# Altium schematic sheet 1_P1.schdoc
size 441 x 327 mm; Symbol: Drawing-Symbol_A4; Device: Drawing-Symbol_A4; @Project Name: LC86G-PA Breakout Board V2; @Page Count: 1; @Update Date: 2025-05-25; @Create Date: 2025-05-26; @Schematic Name: Schematic1_1; @Page No: 1; @Page Name: P1; Company: EasyEDA.com; Version: V1.0; Page Size: A4; @Create Time: 00:19:22; @Update Time: 19:19:22; Width: 1700; Height: 1250; Region Start: 1; X Region Count: 6; Y Region Count: 4; Blade Width: 10; Title Block Position: 3; @Board Name: Board1_1
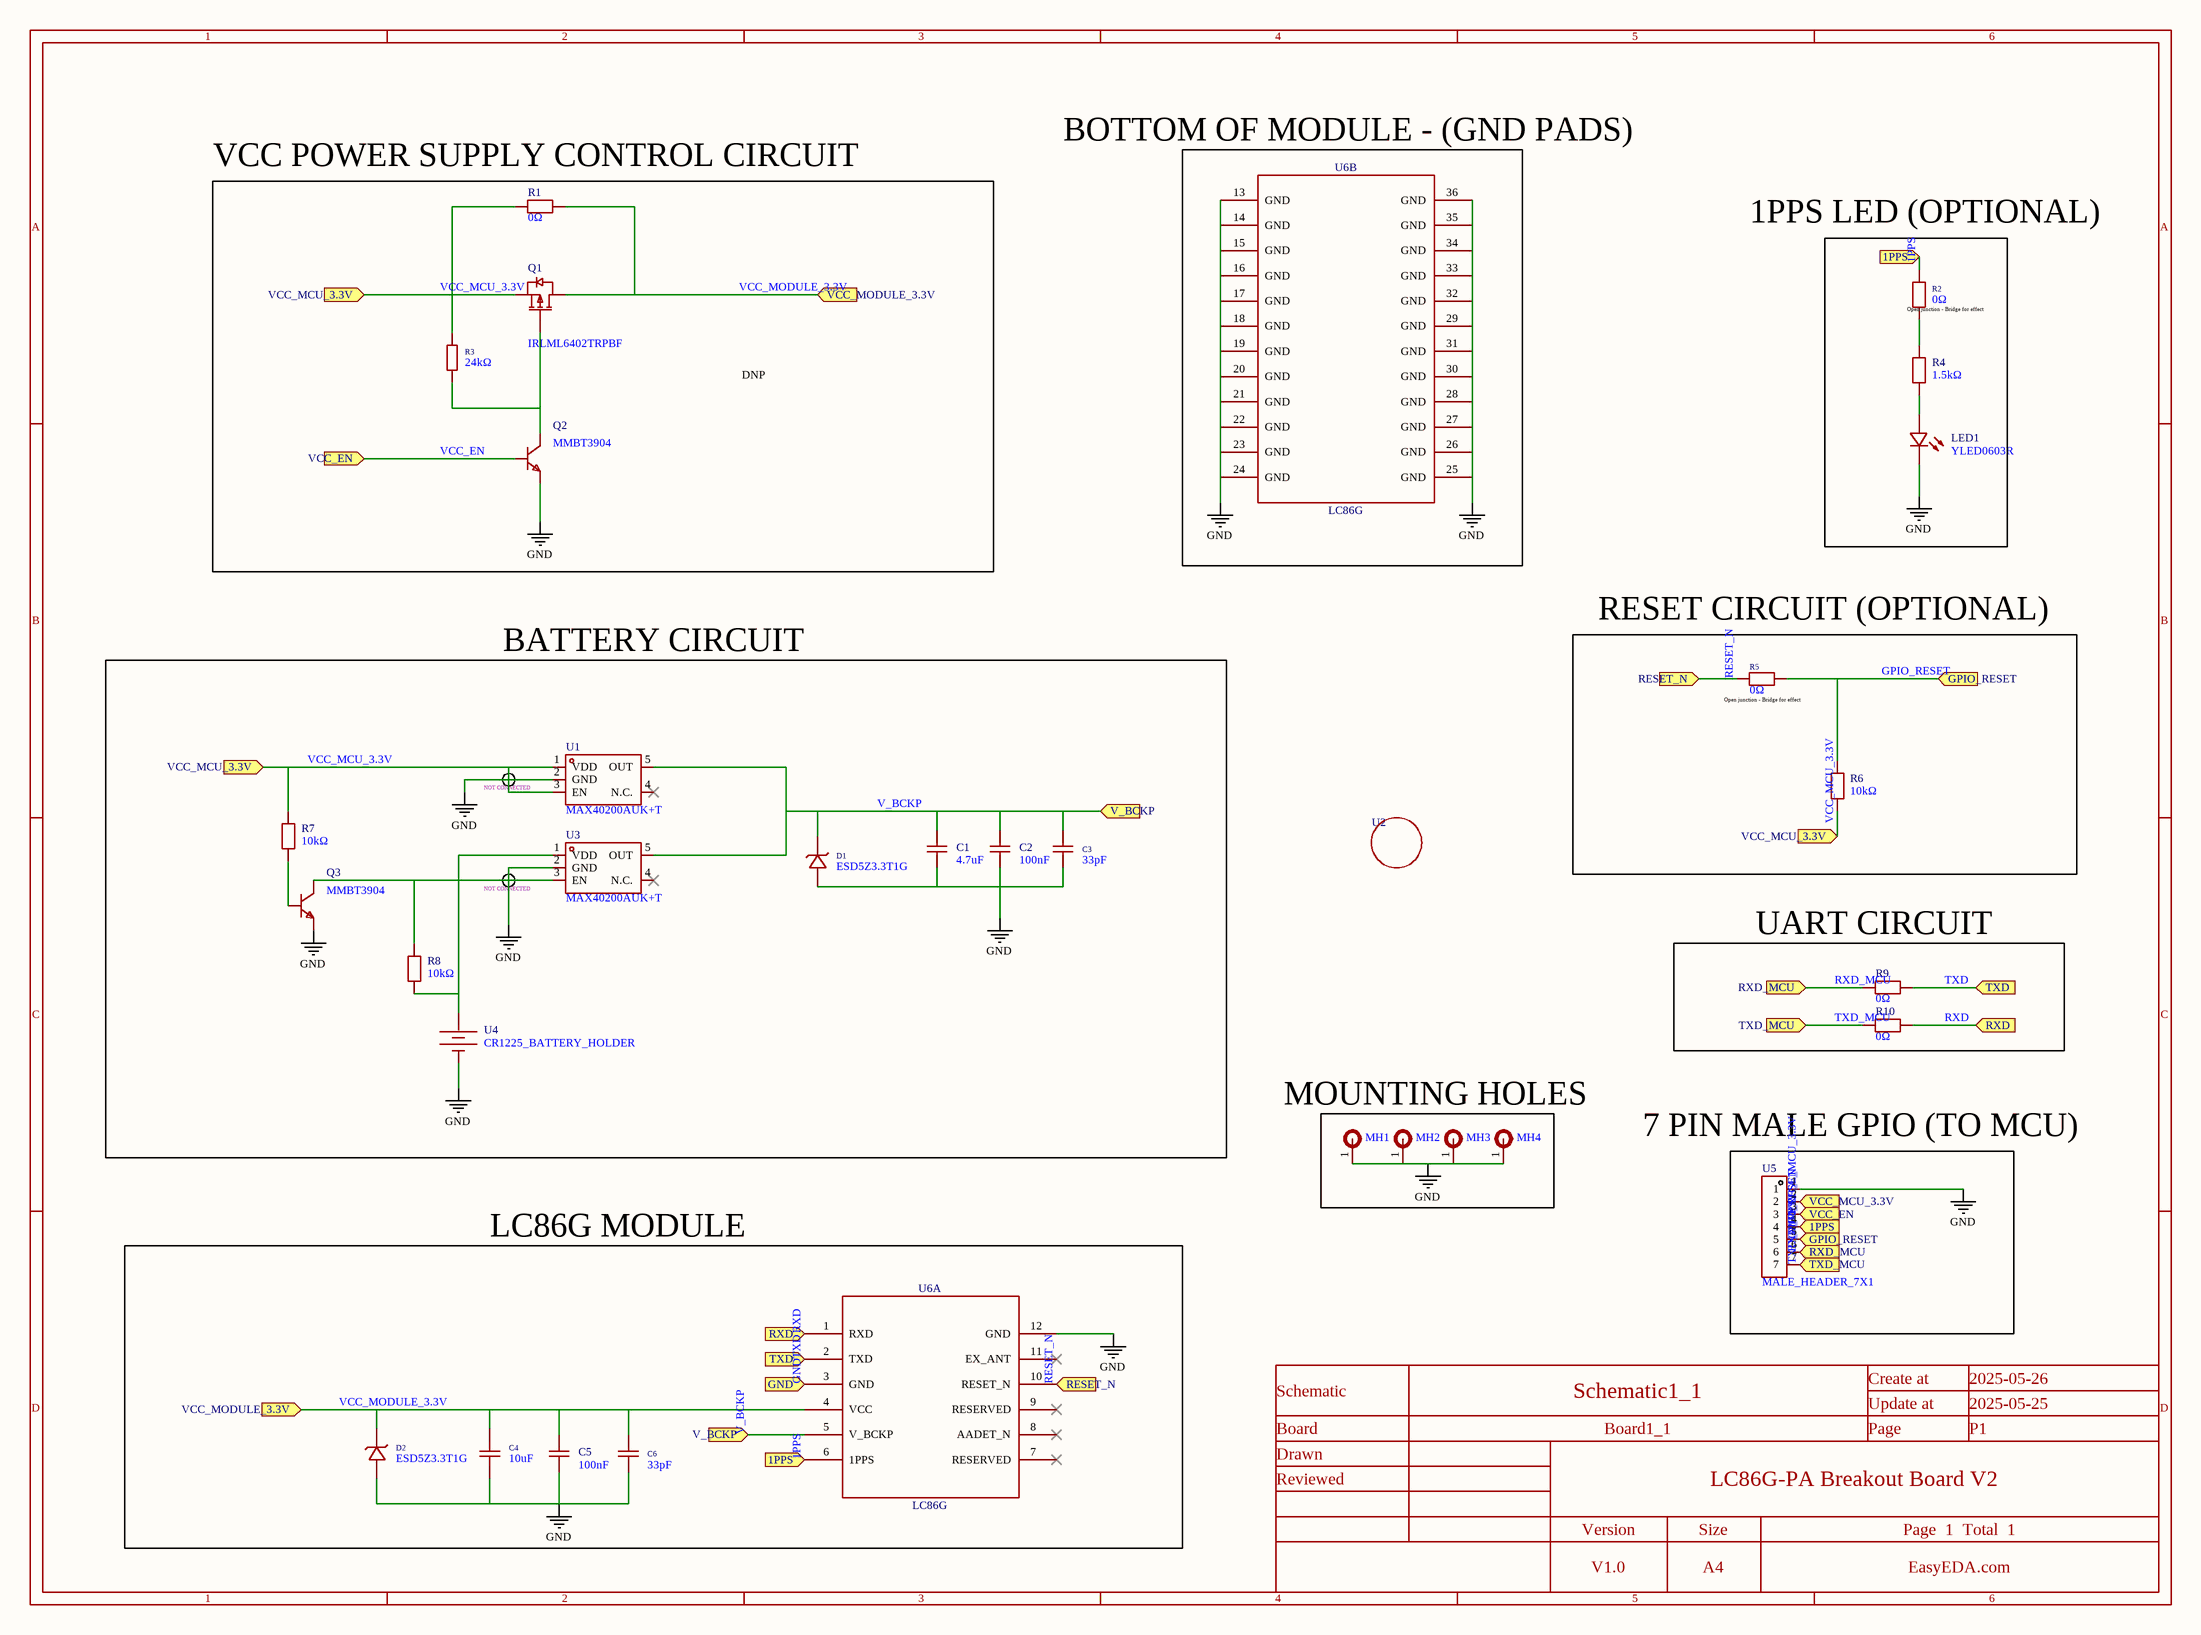
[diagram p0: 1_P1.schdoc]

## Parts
C1  4.7uF  [C0603]
C2  100nF  [C0603]
C3  33pF  [C0603]
C4  10uF  [C0603]
C5  100nF  [C0603]
C6  33pF  [C0603]
D1  ESD5Z3.3T1G  [SOD-523F_L1.2-W0.8-LS1.7-RD]
D2  ESD5Z3.3T1G  [SOD-523F_L1.2-W0.8-LS1.7-RD]
LED1  YLED0603R  [LED0603-FD]
MH1  (no value)  [MH_7.5x2.7MM]
MH2  (no value)  [MH_7.5x2.7MM]
MH3  (no value)  [MH_7.5x2.7MM]
MH4  (no value)  [MH_7.5x2.7MM]
Q1  IRLML6402TRPBF  [SOT-23-3_L2.9-W1.6-P1.90-LS2.8-BR]
Q2  MMBT3904  [SOT-23-3_L2.9-W1.4-P1.90-LS2.6-BR]
Q3  MMBT3904  [SOT-23-3_L2.9-W1.4-P1.90-LS2.6-BR]
R1  0Ω  [R0603]
R2  0Ω  [R0201]
R3  24kΩ  [R0603]
R4  1.5kΩ  [R0603]
R5  0Ω  [R0201]
R6  10kΩ  [R0603]
R7  10kΩ  [R0603]
R8  10kΩ  [R0603]
R9  0Ω  [R0603]
R10  0Ω  [R0603]
U1  MAX40200AUK+T  [TSOT-23-5_L2.9-W1.6-P0.95-LS2.8-BL]
U2  (no value)  [KEEPOUT HOLEf]
U3  MAX40200AUK+T  [TSOT-23-5_L2.9-W1.6-P0.95-LS2.8-BL]
U4  CR1225_BATTERY_HOLDER  [BAT-SMD_BS-12-B3AA011]
U5  MALE_HEADER_7X1  [HDR-TH_7P-P2.54-V-M]
U6  LC86G  [LC86G]  (parts A,B of 2)

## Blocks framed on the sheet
VCC POWER SUPPLY CONTROL CIRCUIT: Q1 Q2 R1 R3
Open junction - Bridge for effect: LED1 R2 R4
RESET CIRCUIT (OPTIONAL): R5 R6
BATTERY CIRCUIT: C1-C3 D1 Q3 R7 R8 U1 U3 U4
UART CIRCUIT: R9 R10
LC86G MODULE: C4-C6 D2 U6

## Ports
1PPS (in), GND (in), GPIO_RESET (in), RESET_N (in), RXD (in), RXD_MCU (in), TXD (in), TXD_MCU (in), V_BCKP (in), VCC_EN (in), VCC_MCU_3.3V (in), VCC_MODULE_3.3V (in)

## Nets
GND: C1.1 C2.1 C3.1 C4.1 C5.1 C6.1 D1.2 D2.2 LED1.2(-) MH1.1 MH2.1 MH3.1 MH4.1 Q2.2(E) Q3.2(E) U1.2(GND) U3.2(GND) U4.2(-) U5.1 U6.3(GND) U6.12(GND) U6.13(GND) U6.14(GND) U6.15(GND) U6.16(GND) U6.17(GND) U6.18(GND) U6.19(GND) U6.20(GND) U6.21(GND) U6.22(GND) U6.23(GND) U6.24(GND) U6.25(GND) U6.26(GND) U6.27(GND) U6.28(GND) U6.29(GND) U6.30(GND) U6.31(GND) U6.32(GND) U6.33(GND) U6.34(GND) U6.35(GND) U6.36(GND) ; port GND
1PPS: R2.2 U5.4 U6.6(1PPS) ; port 1PPS
GPIO_RESET: R5.2 R6.2 U5.5 ; port GPIO_RESET
RESET_N: R5.1 U6.10(RESET_N) ; port RESET_N
RXD: R10.1 U6.1(RXD) ; port RXD
RXD_MCU: R9.2 U5.6 ; port RXD_MCU
TXD: R9.1 U6.2(TXD) ; port TXD
TXD_MCU: R10.2 U5.7 ; port TXD_MCU
V_BCKP: C1.2 C2.2 C3.2 D1.1 U1.5(OUT) U3.5(OUT) U6.5(V_BCKP) ; port V_BCKP
VCC_EN: Q2.1(B) U5.3 ; port VCC_EN
VCC_MCU_3.3V: Q1.2(S) R1.2 R3.2 R6.1 R7.1 U1.1(VDD) U1.3(EN) U5.2 ; port VCC_MCU_3.3V
VCC_MODULE_3.3V: C4.2 C5.2 C6.2 D2.1 Q1.3(D) R1.1 U6.4(VCC) ; port VCC_MODULE_3.3V
NetLED1_1: LED1.1(+) R4.1
NetQ1_1: Q1.1(G) Q2.3(C) R3.1
NetQ3_1: Q3.1(B) R7.2
NetQ3_3: Q3.3(C) R8.2 U3.3(EN)
NetR2_1: R2.1 R4.2
NetR8_1: R8.1 U3.1(VDD) U4.1(+)

Not connected (* = marked no-connect by the designer): U1 4(N.C.)*; U3 4(N.C.)*; U6 7(RESERVED)* 8(AADET_N)* 9(RESERVED)* 11(EX_ANT)*

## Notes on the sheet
- BOTTOM OF MODULE - (GND PADS)
- 1PPS LED (OPTIONAL)
- DNP
- (near R5) Open junction - Bridge for effect
- (near U1) NOT CONNECTED
- (near U3) NOT CONNECTED
- MOUNTING HOLES
- (near U5) 7 PIN MALE GPIO (TO MCU)

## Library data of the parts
C1 = CL10A475KA8NQNC: Manufacturer: SAMSUNG(三星); Add into BOM: yes; Tolerance: ±10%
C2 C5 = 0603B104K500NT_C30926: Manufacturer: FH(风华); Add into BOM: yes; Tolerance: ±10%; Voltage Rating: 50V; Temperature Coefficient: X7R
C3 C6 = CC0603JRNPO9BN330: Manufacturer: YAGEO(国巨); Add into BOM: yes; Tolerance: ±5%
C4 = GRM188R61E106KA73D: Manufacturer: muRata(村田); Add into BOM: yes; Tolerance: ±10%
D1 D2 = ESD5Z3.3T1G_C61148: Manufacturer: onsemi(安森美); Add into BOM: yes; polarity: Unidirectional; Reverse Stand-Off Voltage (Vrwm): 3.3V; Maximum Clamping Voltage: 14.1V; Peak Pulse Current (Ipp)@10/1000us: 11.2A; Breakdown Voltage: 5V; Type: ESD
LED1 = YLED0603R: Manufacturer: YONGYUTAI(永裕泰); Add into BOM: yes; Emitted Color: Red; Forward Voltage (VF): 1.8V~2.4V; Forward Current: 25mA; Dominant Wavelength: 620nm~625nm
MH1-MH4 = MH_7.5x2.7MM: Add into BOM: no; Convert to PCB: yes
Q1 = IRLML6402TRPBF_C2593: Manufacturer: Infineon(英飞凌); Add into BOM: yes; Type: 1 Piece P-Channel; Drain Source On Resistance (RDS(on)@Vgs,Id): 0.065Ω@4.5V,3.7A; Gate Threshold Voltage (Vgs(th)@Id): 0.55V@250uA; Total Gate Charge (Qg@Vgs): 12nC; Input Capacitance (Ciss@Vds): 633pF; Reverse Transfer Capacitance (Crss@Vds): 110pF
Q2 Q3 = MMBT3904_C2848176: Manufacturer: IDCHIP(英锐芯); Add into BOM: yes
R1 R9 R10 = FRC0603F0000TS: Manufacturer: FOJAN(富捷); Add into BOM: yes; Tolerance: ±1%; Power(Watts): 100mW; Voltage-Supply(Max): 75V
R2 R5 = 0201WMF0000TEE: Manufacturer: UNI-ROYAL(厚声); Add into BOM: yes; Tolerance: ±1%
R3 = 0603WAF2402T5E: Manufacturer: UNI-ROYAL(厚声); Add into BOM: yes; Tolerance: ±1%; Temperature Coefficient: ±100ppm/℃
R4 = TD03G1501BT: Manufacturer: FH(风华); Add into BOM: yes; Tolerance: ±0.1%; Temperature Coefficient: ±25ppm/℃
R6-R8 = FRC0603J103 TS: Manufacturer: FOJAN(富捷); Add into BOM: yes; Tolerance: ±5%; Power(Watts): 0.1W; Voltage-Supply(Max): 75V; Temperature Coefficient: ±100ppm/℃
U1 U3 = MAX40200AUK+T: Manufacturer: ADI(亚德诺)/MAXIM(美信); Add into BOM: yes; Output Current: 1.2A; Input Voltage: 1.5V~5.5V
U2 = KEEPOUT HOLE: Add into BOM: no; Convert to PCB: yes
U4 = BS-12-B3AA013: Manufacturer: MYOUNG(美阳); Add into BOM: yes; Connector Type: Battery holder; Battery Type: CR1225
U5 = HB-PH3-25417PB2GOP: Manufacturer: HANBO(汉博); Add into BOM: yes; Pin Structure: 1x7P; Pitch: 2.54mm; Circluar Pins/Square Pins: Policy; Current Rating: 3A; Voltage Rating (Max): 250V
U6 = LC86G: Manufacturer: Quectel; Part Description: LC86G Module 36PIN 16X16mm H6.98mm RO; Geometry_Height: 6.98mm; Add into BOM: yes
